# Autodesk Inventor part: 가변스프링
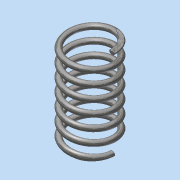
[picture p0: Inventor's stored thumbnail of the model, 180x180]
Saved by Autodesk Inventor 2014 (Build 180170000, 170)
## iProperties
Created: 2022-08
Part Number: 가변스프링
Material: 스테인레스 스틸
Document SubType Name: Modeling
Designer: dg
Density: 8.08 g/cm^3
Appearance: 반연마
Mass: 70.5045 g
Surface Area: 88.3584 cm^2
Volume: 8.7258 cm^3
Author: dg
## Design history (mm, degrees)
sketch "스케치1"
  geometry: L1 (0, 0)-(0, 64); L2 (0, 0)-(16, 0); L3 (0, 64)-(16, 64); C1 r 2 at (16, 0)
  constraints: 6 end point, 1 centre point, 1 coincident, 1 parallel, 1 perpendicular, 1 vertical, 1 vertical alignment
  dimensions: "d0" = 64 distance of L1.start L1.end (derived); "d1" = 32 diameter of L2.end L1; "d2" = 4 diameter of C1
feature "코일1" pitch "d3" = 10; turns "d5" = 7; dims "d4" = 64 (= d0), "d6" = 0, angle "d7" = 90 deg, angle "d8" = 90 deg, "d9" = 0, "d10" = 0
node "작업 평면1"
node "작업 평면2"
feature "분할1"
feature "분할2"
node "솔리드1"
other parameters: "d11" = 0, "d12" = 0
